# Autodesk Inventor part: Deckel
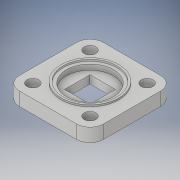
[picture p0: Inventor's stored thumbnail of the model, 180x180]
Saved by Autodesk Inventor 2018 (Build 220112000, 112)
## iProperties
Created: 2018-09
Part Number: Deckel
Material: Generisch
Document SubType Name: Modeling
Designer: mathes
Density: 1 g/cm^3
Appearance: Vorgabe
Author: mathes
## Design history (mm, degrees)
sketch "Skizze1"
  geometry: L1 (-12.5, 12.5)-(12.5, 12.5); L2 (12.5, 12.5)-(12.5, -12.5); L3 (12.5, -12.5)-(-12.5, -12.5); L4 (-12.5, -12.5)-(-12.5, 12.5); 1 further point
  constraints: 8 end point, 2 parallel, 1 horizontal, 1 perpendicular
  dimensions: "d0" = 12.5 distance from line of L1 point (0, 0); "d1" = 12.5 distance from line of L3 point (0, 0); "d2" = 12.5 distance from line of L2 point (0, 0); "d3" = 12.5 distance from line of L4 point (0, 0)
extrude "Extrusion1" new body sketch "Skizze1" distance "d4" = 4; taper "d5" = 0 deg
fillet "Rundung1" dims "d6" = 4
sketch "Skizze2"
  geometry: L1 (-3.8, 3.8)-(3.8, 3.8); L2 (3.8, 3.8)-(3.8, -3.8); L3 (3.8, -3.8)-(-3.8, -3.8); L4 (-3.8, -3.8)-(-3.8, 3.8); 1 further point
  constraints: 8 end point, 2 parallel, 1 horizontal, 1 perpendicular
  dimensions: "d32" = 3.8 distance from line of L4 point (0, 0); "d33" = 3.8 distance from line of L2 point (0, 0); "d34" = 3.8 distance from line of L1 point (0, 0); "d35" = 3.8 distance from line of point (0, 0) L3
extrude "Extrusion2" cut sketch "Skizze2" distance "d8" = 5; taper "d9" = 0 deg
sketch "Skizze3"
  geometry: C1 r 7 at (0, 0); 1 further point
  constraints: 1 centre point, 1 coincident
  dimensions: "d10" = 14 diameter of C1
extrude "Extrusion3" cut sketch "Skizze3" distance "d11" = 1.6; taper "d12" = 0 deg
sketch "Skizze4"
  geometry: 5 further points
  dimensions: "d13" = 8.5 horizontal distance of point (0, 0) point (-8.5, 8.5); "d14" = 8.5 horizontal distance of point (-8.5, 8.5) point (0, 0); "d15" = 8.5 horizontal distance of point (0, 0) point (8.5, 8.5); "d16" = 8.5 horizontal distance of point (8.5, 8.5) point (0, 0); "d17" = 8.5 horizontal distance of point (0, 0) point (8.5, -8.5); "d18" = 8.5 horizontal distance of point (0, 0) point (8.5, -8.5); "d19" = 8.5 horizontal distance of point (0, 0) point (-8.5, -8.5); "d20" = 8.5 horizontal distance of point (0, 0) point (-8.5, -8.5)
hole "Bohrung1" sketch "Skizze4" at (-8.5, 8.5), (8.5, 8.5), (8.5, -8.5), (-8.5, -8.5) diameter "d21" = 3.5; stored, may be unused: countersink angle "d25" = 90 deg, drill point angle "d27" = 118 deg; dims "d22" = 6, "d23" = 4, "d24" = 2, "d26" = 8
sketch "Skizze6"
  geometry: C1 r 8 at (0, 0); C2 r 8.6 at (0, 0); 1 further point
  constraints: 2 centre point, 2 coincident
  dimensions: "d38" = 16 diameter of C1; "d39" = 17.2 diameter of C2
extrude "Extrusion5" join sketch "Skizze6" distance "d40" = 0.5; taper "d41" = 0 deg
node "Volumenkörper1"
